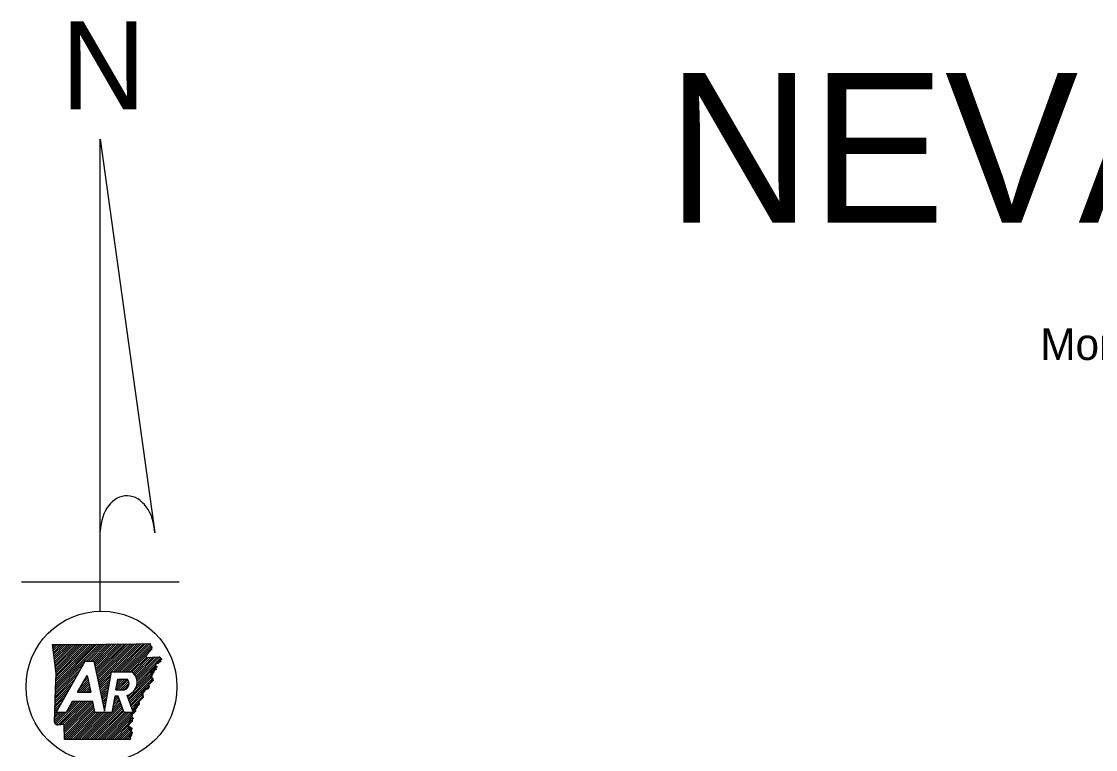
# Model space of a CAD drawing. Extents: x 31699 to 244310, y -8841 to 11474.
# Drawn here: x 91229 to 94816, y -1772 to 658 of the extents above; entities that cross this region are included whole.
import ezdxf

# ---------------------------------------------------------------- set-up
doc = ezdxf.new("R2010")
doc.units = 0
for name, color, linetype in [('G-ANNO-SYMB', 7, 'Continuous'), ('Level 48', 7, 'Continuous'), ('R_Border', 7, 'Continuous')]:
    doc.layers.add(name, color=color, linetype=linetype)

msp = doc.modelspace()

# ---------------------------------------------------------------- linework, layer by layer
at = {"layer": 'Level 48'}
for p, q in [((91491.8, 265.1), (91673.6, -1049)), ((91491.8, -1310.8), (91491.8, 265.1)), ((91228.6, -1213.3), (91754.9, -1213.3)), ((91332.1, -1423.7), (91334.3, -1421.5)), ((91332.9, -1429.9), (91341.3, -1421.5)), ((91333.7, -1436), (91348.2, -1421.5)), ((91334.4, -1442.2), (91355.2, -1421.5)), ((91335.2, -1448.4), (91362.1, -1421.5)), ((91336, -1454.6), (91369.1, -1421.5)), ((91336.7, -1460.8), (91376.1, -1421.5)), ((91337.5, -1467), (91383, -1421.5)), ((91338.3, -1473.2), (91390, -1421.5)), ((91339.1, -1479.4), (91396.9, -1421.5)), ((91339.8, -1485.6), (91403.9, -1421.5)), ((91340.6, -1491.8), (91410.9, -1421.5)), ((91341.4, -1498), (91417.8, -1421.5)), ((91342.1, -1504.2), (91424.8, -1421.5)), ((91342.4, -1573.6), (91494.6, -1421.4)), ((91342.6, -1566.4), (91487.6, -1421.4)), ((91342.9, -1559.2), (91480.6, -1421.4)), ((91342.9, -1510.4), (91431.8, -1421.5)), ((91343.1, -1552), (91473.6, -1421.5)), ((91343.3, -1544.8), (91466.7, -1421.5)), ((91343.6, -1537.6), (91459.7, -1421.5)), ((91343.7, -1516.6), (91438.7, -1421.5)), ((91343.8, -1530.4), (91452.7, -1421.5)), ((91344.1, -1523.2), (91445.7, -1421.5)), ((91445.8, -1477.1), (91501.6, -1421.4)), ((91452.8, -1477.1), (91508.5, -1421.4)), ((91459.8, -1477.1), (91515.6, -1421.3)), ((91466.7, -1477.1), (91522.6, -1421.2)), ((91471.1, -1479.8), (91529.7, -1421.1)), ((91472.3, -1485.5), (91536.8, -1421)), ((91473.5, -1491.2), (91543.9, -1420.9)), ((91474.7, -1497), (91551, -1420.8)), ((91476, -1502.7), (91558, -1420.7)), ((91477.2, -1508.5), (91565.1, -1420.5)), ((91478.4, -1514.2), (91572.2, -1420.4)), ((91479.7, -1519.9), (91579.3, -1420.3)), ((91480.9, -1525.7), (91586.3, -1420.2)), ((91482.1, -1531.4), (91593.4, -1420.1)), ((91483.3, -1537.1), (91600.5, -1420)), ((91484.6, -1542.9), (91607.6, -1419.9)), ((91485.8, -1548.6), (91614.7, -1419.8)), ((91487, -1554.4), (91621.8, -1419.6)), ((91535.4, -1512.9), (91628.9, -1419.4)), ((91542.4, -1512.9), (91636, -1419.3)), ((91549.3, -1512.9), (91643.2, -1419.1)), ((91556.3, -1512.9), (91650.3, -1418.9)), ((91563.3, -1512.9), (91657.4, -1418.8)), ((91570.2, -1512.9), (91659, -1424.2)), ((91577.2, -1512.9), (91662.4, -1427.8)), ((91584.2, -1512.9), (91663.3, -1433.8)), ((91591.1, -1512.9), (91647.4, -1456.7)), ((91597.5, -1513.6), (91646, -1465)), ((91601.3, -1516.7), (91653.3, -1464.7)), ((91604.7, -1520.3), (91660.7, -1464.3)), ((91607.7, -1524.3), (91668, -1463.9)), ((91610.3, -1528.6), (91675.4, -1463.5)), ((91612.4, -1533.5), (91682.7, -1463.2)), ((91614, -1538.8), (91689.3, -1463.5)), ((91614.9, -1544.9), (91692.6, -1467.2)), ((91341.9, -1588), (91427, -1502.9)), ((91342.1, -1580.8), (91436.1, -1486.8)), ((91344.5, -1648.7), (91441.6, -1477.1)), ((91441.6, -1477.1), (91470.5, -1477.1)), ((91613.5, -1560.2), (91676.7, -1497)), ((91615, -1551.8), (91675.9, -1490.8)), ((91668.9, -1511.7), (91677.5, -1503.1)), ((91689.5, -1477.3), (91695.8, -1470.9)), ((91341.4, -1602.4), (91408.9, -1535)), ((91341.7, -1595.2), (91417.9, -1518.9)), ((91415.9, -1581.4), (91447.7, -1525.3)), ((91424.6, -1566.1), (91450.8, -1539.8)), ((91433.7, -1550), (91449.6, -1534.1)), ((91442.8, -1534), (91448.4, -1528.4)), ((91488.2, -1560.1), (91527.8, -1520.6)), ((91489.5, -1565.8), (91526.3, -1529)), ((91490.7, -1571.6), (91524.8, -1537.4)), ((91529.1, -1512.9), (91596.6, -1512.9)), ((91543.8, -1573.8), (91580.4, -1537.2)), ((91545.2, -1565.4), (91573.5, -1537.2)), ((91546.7, -1557), (91566.5, -1537.2)), ((91548.2, -1548.5), (91559.5, -1537.2)), ((91549.6, -1540.1), (91552.6, -1537.2)), ((91550.1, -1537.2), (91581.8, -1537.2)), ((91550.8, -1573.8), (91584.3, -1540.2)), ((91584.8, -1602.9), (91662, -1525.7)), ((91586.6, -1608), (91663.3, -1531.3)), ((91588.5, -1613.1), (91664.6, -1537)), ((91607.5, -1573.2), (91660.7, -1520)), ((91340.9, -1616.8), (91390.7, -1567.1)), ((91341.2, -1609.6), (91399.8, -1551.1)), ((91416.3, -1581.4), (91452.1, -1545.6)), ((91423.2, -1581.4), (91453.3, -1551.3)), ((91430.2, -1581.4), (91454.5, -1557.1)), ((91437.2, -1581.4), (91455.7, -1562.8)), ((91444.1, -1581.4), (91457, -1568.5)), ((91451.1, -1581.4), (91458.2, -1574.3)), ((91491.9, -1577.3), (91523.4, -1545.9)), ((91493.2, -1583), (91521.9, -1554.3)), ((91494.4, -1588.8), (91520.4, -1562.7)), ((91495.6, -1594.5), (91519, -1571.2)), ((91543.8, -1573.8), (91572.7, -1573.8)), ((91557.7, -1573.8), (91586.7, -1544.9)), ((91564.7, -1573.8), (91588, -1550.5)), ((91571.7, -1573.8), (91587.4, -1558.1)), ((91590.4, -1618.2), (91665.9, -1542.7)), ((91642.1, -1573.4), (91651.9, -1563.7)), ((91340.5, -1631.2), (91372.5, -1599.2)), ((91340.7, -1624), (91381.6, -1583.2)), ((91341.5, -1685.9), (91414.7, -1612.7)), ((91345.6, -1688.8), (91421.7, -1612.7)), ((91350.6, -1690.7), (91428.6, -1612.7)), ((91358.9, -1689.4), (91435.6, -1612.7)), ((91366, -1689.3), (91442.6, -1612.7)), ((91371.4, -1690.8), (91449.5, -1612.7)), ((91371.7, -1704.5), (91463.5, -1612.7)), ((91371.7, -1697.6), (91456.5, -1612.7)), ((91398.2, -1612.7), (91377.8, -1648.7)), ((91385.7, -1634.8), (91407.7, -1612.7)), ((91394.8, -1618.7), (91400.8, -1612.7)), ((91466.4, -1612.7), (91398.2, -1612.7)), ((91415.9, -1581.4), (91459.7, -1581.4)), ((91458.1, -1581.4), (91459.4, -1580)), ((91496.8, -1600.3), (91517.5, -1579.6)), ((91498.1, -1606), (91516, -1588.1)), ((91499.3, -1611.7), (91514.5, -1596.5)), ((91500.5, -1617.5), (91513.1, -1604.9)), ((91501.8, -1623.2), (91511.6, -1613.4)), ((91531.9, -1641.8), (91559.4, -1614.4)), ((91533.4, -1633.4), (91557.5, -1609.3)), ((91534.8, -1625), (91555.6, -1604.2)), ((91536.3, -1616.5), (91553.7, -1599.1)), ((91537.8, -1608.1), (91551.7, -1594.2)), ((91539.2, -1599.6), (91544.7, -1594.2)), ((91551.9, -1594.2), (91540.2, -1594.2)), ((91572.1, -1648.7), (91551.9, -1594.2)), ((91580.5, -1591.2), (91601.7, -1648.7)), ((91581, -1592.7), (91583.1, -1590.6)), ((91582.9, -1597.8), (91596.1, -1584.5)), ((91592.3, -1623.2), (91634.1, -1581.5)), ((91594.2, -1628.3), (91633.3, -1589.2)), ((91596, -1633.4), (91632.5, -1596.9)), ((91338.9, -1681.6), (91371.7, -1648.7)), ((91339, -1674.5), (91364.8, -1648.7)), ((91339.3, -1667.3), (91357.8, -1648.7)), ((91339.5, -1660.1), (91350.8, -1648.7)), ((91339.8, -1652.9), (91345.2, -1647.4)), ((91340, -1645.7), (91354.3, -1631.4)), ((91340.2, -1638.5), (91363.4, -1615.3)), ((91377.8, -1648.7), (91344.5, -1648.7)), ((91371.7, -1711.4), (91467.1, -1616)), ((91371.7, -1718.4), (91468.4, -1621.8)), ((91371.8, -1725.3), (91469.6, -1627.5)), ((91371.8, -1732.3), (91470.8, -1633.2)), ((91371.9, -1739.1), (91472.1, -1639)), ((91378.8, -1739.2), (91473.3, -1644.7)), ((91385.8, -1739.2), (91476.2, -1648.7)), ((91392.8, -1739.2), (91483.2, -1648.7)), ((91399.7, -1739.2), (91490.2, -1648.7)), ((91406.7, -1739.2), (91497.1, -1648.7)), ((91413.6, -1739.2), (91504.1, -1648.7)), ((91420.6, -1739.2), (91511.1, -1648.7)), ((91427.5, -1739.2), (91518, -1648.7)), ((91434.5, -1739.2), (91525, -1648.7)), ((91441.4, -1739.3), (91561.2, -1619.4)), ((91448.4, -1739.3), (91563.1, -1624.5)), ((91455.3, -1739.3), (91565, -1629.6)), ((91462.3, -1739.3), (91566.9, -1634.7)), ((91469.2, -1739.3), (91568.8, -1639.8)), ((91530.7, -1648.7), (91474.1, -1648.7)), ((91476.2, -1739.3), (91570.6, -1644.9)), ((91483.2, -1739.3), (91573.7, -1648.7)), ((91490.1, -1739.3), (91580.7, -1648.7)), ((91497.1, -1739.3), (91587.7, -1648.7)), ((91503, -1628.9), (91510.1, -1621.8)), ((91504, -1739.4), (91594.6, -1648.7)), ((91504.2, -1634.7), (91508.7, -1630.2)), ((91505.4, -1640.4), (91507.2, -1638.7)), ((91601.7, -1648.7), (91572.1, -1648.7)), ((91597.9, -1638.5), (91619.3, -1617.1)), ((91599.8, -1643.6), (91616.3, -1627.1)), ((91511, -1739.4), (91597, -1653.4)), ((91517.9, -1739.4), (91597.3, -1660)), ((91524.9, -1739.4), (91597.6, -1666.7)), ((91531.8, -1739.4), (91597.9, -1673.3)), ((91538.8, -1739.4), (91586.5, -1691.7)), ((91545.7, -1739.4), (91588.6, -1696.6)), ((91552.7, -1739.4), (91590.8, -1701.4)), ((91559.7, -1739.4), (91592.9, -1706.2)), ((91566.6, -1739.5), (91595.1, -1711)), ((91573.6, -1739.5), (91596.9, -1716.2)), ((91580.5, -1739.5), (91593.7, -1726.3)), ((91587.5, -1739.5), (91590.6, -1736.4))]:
    msp.add_line(p, q, dxfattribs=at)
for points in [[(91331.8, -1421.5), (91427.9, -1421.5), (91512.3, -1421.4), (91611.8, -1419.8), (91657.9, -1418.8)], [(91331.8, -1421.5), (91427.9, -1421.5), (91512.3, -1421.4), (91611.8, -1419.8), (91657.9, -1418.8)], [(91342.5, -1570.9), (91344.1, -1520.3), (91331.8, -1421.5)], [(91338.8, -1681.5), (91344.2, -1520.3), (91331.8, -1421.5)], [(91688.1, -1462.9), (91696.4, -1471.6), (91675.7, -1488.6), (91677.9, -1505.8), (91660.1, -1517.6), (91666.2, -1544), (91652.5, -1556.5), (91651.3, -1570.1), (91634.6, -1576.1), (91632, -1601.8), (91620, -1614.6), (91614.2, -1633.9), (91596.8, -1649.9), (91598.1, -1678), (91586.3, -1691.3), (91597.1, -1715.5), (91589.6, -1739.5)], [(91643.6, -1465.1), (91688.7, -1462.9)], [(91643.6, -1465.2), (91688.7, -1462.9)], [(91470.5, -1477.1), (91506.2, -1644.1), (91529.1, -1512.9)], [(91447.7, -1525.3), (91459.7, -1581.4)], [(91543.8, -1573.8), (91550.1, -1537.2)], [(91338.8, -1681.5), (91342.5, -1570.9)], [(91474.1, -1648.7), (91466.4, -1612.7)], [(91540.2, -1594.2), (91530.7, -1648.7)], [(91589.6, -1739.5), (91371.8, -1739.1), (91371.7, -1691.1)], [(91589.6, -1739.5), (91371.8, -1739.1), (91371.7, -1691.1)]]:
    msp.add_lwpolyline(points, dxfattribs=at)
for centre, major_axis, ratio, start_param, end_param in [((91582.6, -1051.9), (-3.9, 126.3), 0.719778, 4.712385, 7.768526), ((91565.8, -1552.6), (-22.3, 0), 0.999987, 1.887169, 3.90762), ((91571.5, -1548.6), (-43.6, 0), 0.999987, 1.777838, 4.099264)]:
    msp.add_ellipse(centre, major_axis=major_axis, ratio=ratio, start_param=start_param, end_param=end_param, dxfattribs=at)
msp.add_ellipse((91495.9, -1562.8), major_axis=(252.1, 0), ratio=0.999976, dxfattribs=at)
for points in [[(91657.9, -1418.8), (91658.2, -1421.4), (91659, -1422.7), (91659.1, -1425.2), (91660.1, -1426.3), (91661.9, -1427.4), (91663.4, -1429.1), (91663.8, -1431.1), (91663.3, -1433.2), (91663.2, -1435.5), (91662.9, -1437.6), (91662.5, -1439.4), (91661.2, -1440.9), (91659.8, -1441.9), (91658.6, -1443.1), (91657.7, -1444.5), (91656.1, -1445.9), (91654.6, -1447.4), (91653.3, -1448.7), (91652, -1450.4), (91651.4, -1452.2), (91650.1, -1453.5), (91649, -1454.7), (91647.6, -1456.3), (91646.9, -1457.9), (91645.6, -1459.8), (91645.2, -1461.5), (91644.4, -1462.9), (91644.3, -1463.2)], [(91657.9, -1418.8), (91658.2, -1421.4), (91659, -1422.7), (91659.1, -1425.2), (91660.1, -1426.3), (91661.9, -1427.4), (91663.4, -1429.1), (91663.8, -1431.1), (91663.3, -1433.2), (91663.2, -1435.5), (91662.9, -1437.5), (91662.6, -1439.4), (91661.2, -1440.9), (91659.8, -1441.9), (91658.5, -1443.2), (91657.6, -1444.5), (91656.1, -1445.9), (91654.6, -1447.4), (91653.3, -1448.7), (91652.1, -1450.4), (91651.5, -1452.2), (91650.1, -1453.5), (91649, -1454.7), (91647.6, -1456.3), (91646.9, -1457.9), (91645.5, -1459.8), (91645.2, -1461.5), (91644.3, -1463), (91644.3, -1463.2)], [(91688.1, -1462.9), (91688.7, -1462.9), (91690.7, -1465), (91691.6, -1466.8), (91693, -1467.8), (91694.5, -1468.3), (91695.6, -1469.7), (91696.3, -1471.2), (91695.9, -1472.5), (91694.2, -1472.6), (91692.4, -1472.9), (91690.6, -1472.8), (91689.2, -1474.1), (91690.5, -1475.6), (91692.2, -1477.1), (91692.7, -1478.7), (91691.8, -1480.2), (91689.8, -1481.1), (91688, -1481.8), (91686.3, -1483.2), (91685.5, -1484.6), (91683.7, -1485.2), (91681.8, -1485.7), (91680.2, -1485.9), (91678.3, -1486.3), (91676.4, -1487.2), (91675.7, -1488.7), (91675.9, -1490.9), (91675.8, -1493.2), (91677.8, -1494), (91679.5, -1494.1), (91681.2, -1494.9), (91681, -1496.2), (91679.8, -1497.9), (91678.3, -1499.2), (91676.8, -1499.9), (91675.4, -1501.1), (91675.9, -1502.4), (91677.1, -1503.2), (91678, -1504.6), (91677.9, -1505.8), (91676.5, -1506.7), (91674.9, -1506.3), (91673.8, -1504.9), (91672.5, -1504.4), (91671.4, -1503.9), (91670.1, -1504.6), (91670.1, -1506.3), (91669.6, -1508.2), (91670, -1509.5), (91670.5, -1511.4), (91670.5, -1512.9), (91670, -1514.9), (91669, -1517), (91667.8, -1517.6), (91667.3, -1515.4), (91667.1, -1513.6), (91666.4, -1512.5), (91665.4, -1512.4), (91664.2, -1513.3), (91662.8, -1514.7), (91661.1, -1516.2), (91660.1, -1517.6), (91660.6, -1519.5), (91661.9, -1519.9), (91662.9, -1519.6), (91663.5, -1518.4), (91664.4, -1518.3), (91665.4, -1520.1)], [(91665.4, -1520.1), (91665.7, -1521.8), (91664.7, -1523.6), (91664.3, -1525.5), (91664.4, -1527.3), (91662.5, -1528.3), (91660.9, -1529.5), (91661.9, -1531), (91663.7, -1532.3), (91665.4, -1533.2), (91666.5, -1534.3), (91666.8, -1536.7), (91667.1, -1538.3), (91667.8, -1540.4), (91668, -1541.9), (91666.9, -1543.7), (91665.7, -1544), (91664.3, -1543.6), (91662.8, -1543.5), (91661.6, -1544.6), (91660.7, -1546.4), (91659.8, -1548), (91659.1, -1549.4), (91658.4, -1551), (91657.2, -1552.8), (91655.6, -1553.1), (91653.7, -1553.6), (91652.5, -1554.8), (91652.7, -1557), (91653.8, -1558.5), (91654.6, -1560.4), (91655.2, -1562), (91654.9, -1564), (91654.1, -1565.5), (91653, -1566.4), (91652.5, -1568.3), (91651.7, -1569.7), (91651.1, -1570.2), (91649.6, -1570.1), (91648.1, -1569.8), (91646.8, -1569.9), (91645.6, -1570.5), (91644.3, -1570.1), (91643, -1568.7), (91641.9, -1567.6), (91640.7, -1567.2), (91639.4, -1567.9), (91639.3, -1569.8), (91639.8, -1571.9), (91640.4, -1574.6), (91639.8, -1576.2), (91639.6, -1579)], [(91639.6, -1579), (91637.6, -1580.6), (91636.6, -1582.2), (91631.3, -1581.7), (91631.5, -1583.6), (91629.6, -1584.6), (91627.9, -1585.8), (91628.9, -1587.2), (91630.7, -1588.5), (91632.5, -1589.5), (91633.6, -1590.5), (91633.9, -1593), (91634.2, -1594.5), (91634.8, -1596.7), (91635, -1598.1), (91633.9, -1599.9), (91632.7, -1600.3), (91631.4, -1599.8), (91629.9, -1599.7), (91628.6, -1600.9), (91627.7, -1602.6), (91626.8, -1604.3), (91626.2, -1605.7), (91625.5, -1607.2), (91624.2, -1609), (91622.6, -1609.3), (91620.7, -1609.8), (91619.6, -1611.1), (91619.8, -1613.3), (91620.8, -1614.8), (91621.6, -1616.6), (91622.2, -1618.2), (91622, -1620.2), (91621.1, -1621.7), (91620.1, -1622.6), (91619.6, -1624.5), (91618.8, -1626), (91618.1, -1626.4), (91616.7, -1626.3), (91615.1, -1626), (91613.8, -1626.1), (91612.6, -1626.8), (91611.3, -1626.4), (91610, -1624.9), (91608.9, -1623.9), (91607.7, -1623.4), (91606.5, -1624.1), (91606.3, -1626.1), (91606.9, -1628.1), (91607.4, -1630.8), (91606.9, -1632.5), (91606.7, -1635.3)], [(91606.7, -1635.3), (91606.5, -1635.3), (91605.5, -1636.7), (91606.1, -1638.8), (91608.4, -1639.6), (91609.4, -1641.6), (91609.5, -1643.4), (91608.7, -1645.8), (91607.7, -1647), (91605.6, -1647.5), (91604, -1647.7), (91603.8, -1650.5), (91603, -1651.8), (91601.8, -1652.2), (91600, -1651.4), (91598.9, -1650.9), (91597.6, -1650.3), (91596, -1649.4), (91594.7, -1649.5), (91595.1, -1652.1), (91595.2, -1652.2), (91596.6, -1654.2), (91598, -1655.8), (91598.7, -1657.6)], [(91606.7, -1635.3), (91606.5, -1635.3), (91605.5, -1636.7), (91606.1, -1638.8), (91608.4, -1639.6), (91609.4, -1641.6), (91609.5, -1643.4), (91608.7, -1645.8), (91607.7, -1647), (91605.6, -1647.5), (91604, -1647.7), (91603.8, -1650.5), (91603, -1651.8), (91601.8, -1652.2), (91600, -1651.4), (91598.9, -1650.9), (91597.6, -1650.3), (91596, -1649.4), (91594.7, -1649.5), (91595.1, -1652.1), (91595.2, -1652.2), (91596.6, -1654.2), (91598, -1655.8), (91598.7, -1657.6)], [(91371.7, -1691.1), (91371.9, -1691.2), (91370.8, -1690.4), (91369.2, -1689.6), (91367.5, -1689.5), (91365.3, -1689.2), (91363.5, -1689.1), (91361.6, -1687.8), (91359.6, -1689.1), (91357.3, -1690.1), (91356, -1689), (91354.3, -1689.7), (91353.1, -1689.3), (91351, -1690.8), (91349, -1690.2), (91347.6, -1690.6), (91345.8, -1690.6), (91345.5, -1688.6), (91343.7, -1688.3), (91342.2, -1687.4), (91341.2, -1685.4), (91340.5, -1683.7), (91338.8, -1681.5)], [(91371.7, -1691.1), (91371.9, -1691.2), (91370.8, -1690.4), (91369.2, -1689.6), (91367.5, -1689.5), (91365.3, -1689.2), (91363.5, -1689), (91361.6, -1687.8), (91359.5, -1689.1), (91357.3, -1690.1), (91356, -1689), (91354.3, -1689.7), (91353.1, -1689.3), (91351, -1690.8), (91349, -1690.2), (91347.6, -1690.6), (91345.8, -1690.6), (91345.5, -1688.6), (91343.7, -1688.3), (91342.2, -1687.4), (91341.2, -1685.4), (91340.5, -1683.8), (91338.8, -1681.5)], [(91598.7, -1657.6), (91598.1, -1659), (91597.4, -1661.4), (91597.6, -1663.4), (91598.5, -1665.1), (91599.9, -1666), (91601.5, -1667.4), (91601.4, -1669.5), (91600.5, -1670.2), (91598.4, -1669.8), (91596.8, -1669), (91595.4, -1669.4), (91593.6, -1670.3), (91592.2, -1670.5), (91592.3, -1673.4), (91594.1, -1675.4), (91595.7, -1675.4), (91597.6, -1675.6), (91598.2, -1677.7), (91597.1, -1679.6), (91595.4, -1680.4), (91593.1, -1679.3), (91591.5, -1678.2), (91589.9, -1677.2), (91587.9, -1676.6), (91586.7, -1676.8), (91586.2, -1679.3), (91587.2, -1681.6), (91588.7, -1683.2), (91590.1, -1685.2), (91589.9, -1686.7), (91588.8, -1687.1), (91586.9, -1687.5), (91585.8, -1688.1), (91585.5, -1688.6), (91586.1, -1690.6), (91586.6, -1692.8), (91586.6, -1694.5), (91586, -1696), (91585, -1698.3), (91585.1, -1699.9), (91585.8, -1700.6), (91586.7, -1700.4), (91587.9, -1699.6), (91588.7, -1698.6), (91589.3, -1697.4), (91590.5, -1696.4), (91592.1, -1697.3), (91592.4, -1699.1), (91591.6, -1700.7), (91590.3, -1701.5), (91588.8, -1702.1), (91587.6, -1703.4), (91587.9, -1704.9), (91588.8, -1705.8), (91591, -1705.3), (91592.5, -1704.7), (91593.4, -1703.9), (91594.4, -1702.8), (91594.9, -1701.8), (91595.7, -1700.7), (91597.1, -1700.4), (91597.7, -1701.3), (91597.4, -1703.4), (91596.6, -1705.3), (91595.5, -1706.9), (91594.2, -1708), (91592.7, -1710.4), (91593, -1712.7), (91593.6, -1714.6), (91594.4, -1716), (91595.8, -1715.7), (91597.4, -1715.5), (91598.4, -1716.3), (91598.3, -1717.9), (91597.1, -1719.6), (91596, -1721.1), (91595.4, -1723.2), (91595.6, -1724.7), (91595.6, -1726), (91595.1, -1727.6), (91594.3, -1728.4), (91592.1, -1728.4), (91589.8, -1728.1), (91588.5, -1728.8), (91588.8, -1730.8), (91590.1, -1732.3), (91591.1, -1733.1), (91592.4, -1734.7), (91593, -1736.1), (91592.9, -1737.3), (91592, -1738.4), (91589.6, -1739.5)], [(91598.7, -1657.6), (91598.1, -1659), (91597.4, -1661.4), (91597.6, -1663.4), (91598.5, -1665.1), (91599.9, -1666), (91601.5, -1667.4), (91601.4, -1669.5), (91600.5, -1670.2), (91598.4, -1669.8), (91596.8, -1669), (91595.4, -1669.4), (91593.6, -1670.3), (91592.2, -1670.5), (91592.3, -1673.4), (91594.1, -1675.4), (91595.7, -1675.4), (91597.6, -1675.6), (91598.2, -1677.7), (91597.1, -1679.6), (91595.4, -1680.4), (91593.1, -1679.3), (91591.5, -1678.2), (91589.9, -1677.2), (91587.9, -1676.6), (91586.7, -1676.8), (91586.2, -1679.3), (91587.2, -1681.6), (91588.7, -1683.2), (91590.1, -1685.2), (91589.9, -1686.7), (91588.8, -1687.1), (91586.9, -1687.5), (91585.8, -1688.1), (91585.5, -1688.6), (91586.1, -1690.6), (91586.6, -1692.8), (91586.6, -1694.5), (91586, -1696), (91585, -1698.3), (91585.1, -1699.9), (91585.8, -1700.6), (91586.7, -1700.4), (91587.9, -1699.6), (91588.7, -1698.6), (91589.3, -1697.4), (91590.5, -1696.4), (91592.1, -1697.3), (91592.4, -1699.1), (91591.6, -1700.7), (91590.3, -1701.5), (91588.8, -1702.1), (91587.6, -1703.4), (91587.9, -1704.9), (91588.8, -1705.8), (91591, -1705.3), (91592.5, -1704.7), (91593.4, -1703.9), (91594.4, -1702.8), (91594.9, -1701.8), (91595.7, -1700.7), (91597.1, -1700.4), (91597.7, -1701.3), (91597.4, -1703.4), (91596.6, -1705.3), (91595.5, -1706.9), (91594.2, -1708), (91592.7, -1710.4), (91593, -1712.7), (91593.6, -1714.6), (91594.4, -1716), (91595.8, -1715.7), (91597.4, -1715.5), (91598.4, -1716.3), (91598.3, -1717.9), (91597.1, -1719.6), (91596, -1721.1), (91595.4, -1723.2), (91595.6, -1724.7), (91595.6, -1726), (91595.1, -1727.6), (91594.3, -1728.4), (91592.1, -1728.4), (91589.8, -1728.1), (91588.5, -1728.8), (91588.8, -1730.8), (91590.1, -1732.3), (91591.1, -1733.1), (91592.4, -1734.7), (91593, -1736.1), (91592.9, -1737.3), (91592, -1738.4), (91589.6, -1739.5)]]:
    msp.add_spline(points, degree=3, dxfattribs=at)

# ---------------------------------------------------------------- texts
at = {"layer": 'G-ANNO-SYMB'}
msp.add_text('Morris', height=105.6, dxfattribs=at).set_placement((94631.7, -472.1))
at = {"layer": 'Level 48'}
msp.add_text('N', height=293.3, dxfattribs=at).set_placement((91361, 364.3))
at = {"layer": 'R_Border'}
msp.add_text('NEVADA', height=500, dxfattribs=at).set_placement((93384.1, -13.9))

doc.saveas('drawing.dxf')
